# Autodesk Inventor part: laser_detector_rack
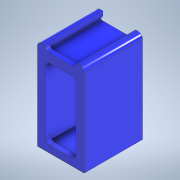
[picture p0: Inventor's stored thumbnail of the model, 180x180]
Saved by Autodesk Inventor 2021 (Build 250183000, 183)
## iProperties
Created: 2026-10
Part Number: laser_detector_rack
Material: Generic
Document SubType Name: Modeling
Designer: alolo
Density: 1 g/cm^3
Appearance: Default
Author: alolo
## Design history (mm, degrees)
sketch "Sketch1"
  geometry: L1 (0, 0)-(20, 0); L2 (20, 0)-(20, 37.1); L3 (0, 37.1)-(0, 0); L4 (20, 37.1)-(20, 35.4); L5 (17.75, 35.4)-(2.25, 35.4); L6 (0, 35.4)-(0, 37.1); L7 (3, 37.1)-(3, 39.1); L8 (17, 37.1)-(17, 39.1); L9 (2, 39.1)-(3, 39.1); L10 (2.25, 37.1)-(3, 37.1); L11 (17, 37.1)-(17.75, 37.1); L12 (17, 39.1)-(18, 39.1); L13 (17.75, 37.1)-(17.75, 35.4); L14 (17.75, 35.4)-(2.25, 35.4); L15 (2.25, 35.4)-(2.25, 37.1); L16 (17.75, 1.4)-(10, 1.4); L17 (17.75, 1.4)-(10, 1.4); L18 (16.5, 3.1)-(17.75, 3.1); L19 (17.75, 3.1)-(17.75, 1.4); L20 (16.5, 33.4)-(10, 33.4); L21 (10, 0)-(10, 35.4); L22 (16.5, 3.1)-(16.5, 33.4); L23 (3.5, 3.1)-(3.5, 33.4); L24 (3.5, 33.4)-(10, 33.4); L25 (2.25, 3.1)-(2.25, 1.4); L26 (2.25, 1.4)-(10, 1.4); L27 (3.5, 3.1)-(2.25, 3.1); A1 r 2 centre (2, 37.1) between (2, 39.1) and (0, 37.1); A2 r 2 centre (18, 37.1) between (20, 37.1) and (18, 39.1); 4 further points
  constraints: 54 end point, 9 perpendicular, 8 point on line, 6 parallel, 5 horizontal, 4 midpoint, 4 point on circle, 4 symmetric about line, 4 tangent, 2 centre point, 2 collinear, 2 vertical, 1 coincident, 1 equal radius, 1 vertical alignment
  dimensions: "d7" = 39.1 distance of L1.end point (20, 39.1); "d8" = 3 distance between parallel lines of L3 L7; "d9" = 3 distance between parallel lines of L2 L8; "d10" = 15.5 distance of L5.start L5.end; "d13" = 2 radius of A1 (derived); "d15" = 1.4 distance between parallel lines of L16 L1; "d16" = 2 distance between parallel lines of L5 L20; "d21" = 7.75 distance of L16.start L16.end; "d22" = 6.5 distance of L20.start L20.end
extrude "Extrusion1" new body sketch "Sketch1" distance "d11" = 25; taper "d12" = 0 deg
sketch "Sketch3"
  geometry: L1 (2.25, 1.4)-(2.25, 3.1) reference; L2 (17.75, 3.1)-(17.75, 1.4) reference; L3 (2.25, 3.1)-(17.75, 3.1); L4 (17.75, 3.1)-(17.75, 1.4); L5 (17.75, 1.4)-(2.25, 1.4); L6 (2.25, 1.4)-(2.25, 3.1); L7 (2.25, 37.1)-(3, 37.1) reference; L8 (17.75, 35.4)-(2.25, 35.4) reference; L9 (2.25, 37.1)-(17.75, 37.1); L10 (17.75, 37.1)-(17.75, 35.4); L11 (17.75, 35.4)-(2.25, 35.4); L12 (2.25, 35.4)-(2.25, 37.1); 5 further points
  constraints: 16 end point, 4 parallel, 2 horizontal, 2 perpendicular
extrude "Extrusion3" join sketch "Sketch3" distance "d23" = 2; taper "d24" = 0 deg
fillet "Fillet3" dims "d25" = 2
body "Solid1"
other parameters: "d4" = 1.7, "d6" = 2
